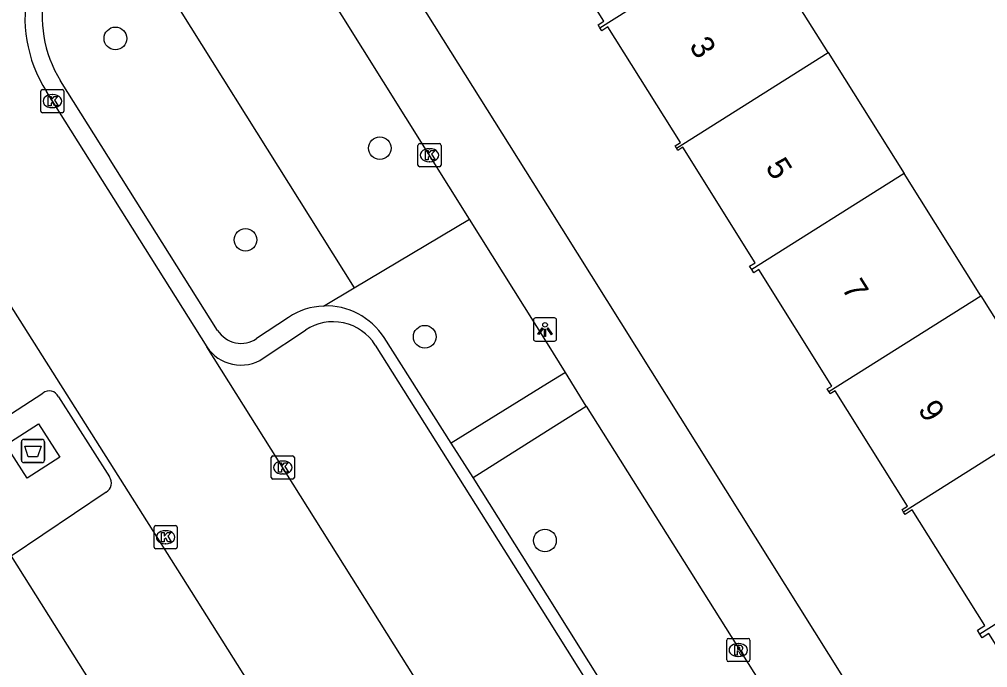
# Model space of a CAD drawing. Extents: x 160077 to 160945, y 386481 to 387498.
# Drawn here: x 160477.21 to 160519, y 386801.35 to 386829.32 of the extents above; entities that cross this region are included whole.
import ezdxf

# ---------------------------------------------------------------- set-up
doc = ezdxf.new("R2010")
doc.units = 0
for name, color, linetype in [('IMGEO_Afval_apart_plaats', 7, 'Continuous'), ('IMGEO_Boom', 7, 'Continuous'), ('IMGEO_Groenvoorziening', 7, 'Continuous'), ('IMGEO_Kolk', 7, 'Continuous'), ('IMGEO_Lichtpunt', 7, 'Continuous'), ('IMGEO_Pand', 7, 'Continuous'), ('IMGEO_Pand_nummerreeks', 7, 'Continuous'), ('IMGEO_Rijbaan_lokaal_open', 7, 'Continuous'), ('IMGEO_Rioolput', 7, 'Continuous'), ('IMGEO_Voetpad_gesloten', 7, 'Continuous'), ('IMGEO_Voetpad_open', 7, 'Continuous')]:
    doc.layers.add(name, color=color, linetype=linetype)

msp = doc.modelspace()

# ---------------------------------------------------------------- linework, layer by layer
at = {"layer": 'IMGEO_Afval_apart_plaats'}
for p, q in [((160477.3, 386810.299), (160477.3, 386811.099)), ((160477.3, 386811.099), (160477.3, 386810.299)), ((160477.4, 386811.199), (160478.19, 386811.199)), ((160478.19, 386811.199), (160477.4, 386811.199)), ((160478.29, 386811.099), (160478.29, 386810.299)), ((160478.29, 386810.299), (160478.29, 386811.099)), ((160478.19, 386810.199), (160477.4, 386810.199)), ((160477.4, 386810.199), (160478.19, 386810.199))]:
    msp.add_line(p, q, dxfattribs=at)
msp.add_lwpolyline([(160477.443, 386810.913), (160478.147, 386810.913), (160477.998, 386810.443), (160477.592, 386810.443), (160477.443, 386810.913)], dxfattribs=at)
for centre, start, end in [((160477.4, 386811.099), 90, 180), ((160477.4, 386811.099), 90, 180), ((160478.19, 386811.099), 0, 90), ((160478.19, 386811.099), 360, 90), ((160477.4, 386810.299), 180, 270), ((160477.4, 386810.299), 180, 270), ((160478.19, 386810.299), 270, 0), ((160478.19, 386810.299), 270, 0)]:
    msp.add_arc(centre, 0.1, start, end, dxfattribs=at)
at = {"layer": 'IMGEO_Boom'}
for centre in [(160481.353, 386828.501), (160492.77, 386823.766), (160486.971, 386819.81), (160494.706, 386815.629), (160499.897, 386806.838)]:
    msp.add_circle(centre, 0.489, dxfattribs=at)
at = {"layer": 'IMGEO_Groenvoorziening'}
for points in [[(160481.322, 386834.24), (160491.654, 386817.735)], [(160491.654, 386817.735), (160496.638, 386820.704)], [(160490.344, 386816.955), (160491.654, 386817.735)]]:
    msp.add_lwpolyline(points, dxfattribs=at)
at = {"layer": 'IMGEO_Kolk'}
for p, q in [((160478.209, 386826.294), (160479.061, 386826.294)), ((160478.134, 386825.368), (160478.134, 386826.22)), ((160478.622, 386826.074), (160478.647, 386826.074)), ((160479.135, 386826.22), (160479.135, 386825.368)), ((160478.645, 386825.514), (160478.62, 386825.514)), ((160479.061, 386825.294), (160478.209, 386825.294)), ((160494.413, 386823.035), (160494.413, 386823.887)), ((160494.488, 386823.961), (160495.34, 386823.961)), ((160495.414, 386823.887), (160495.414, 386823.035)), ((160494.901, 386823.741), (160494.926, 386823.741)), ((160495.34, 386822.961), (160494.488, 386822.961)), ((160494.924, 386823.181), (160494.899, 386823.181)), ((160488.079, 386809.562), (160488.079, 386810.414)), ((160488.154, 386810.488), (160489.006, 386810.488)), ((160489.08, 386810.414), (160489.08, 386809.562)), ((160488.567, 386810.268), (160488.592, 386810.268)), ((160488.59, 386809.708), (160488.565, 386809.708)), ((160489.006, 386809.488), (160488.154, 386809.488)), ((160483.098, 386807.48), (160483.95, 386807.48)), ((160483.023, 386806.554), (160483.023, 386807.406)), ((160483.511, 386807.26), (160483.536, 386807.26)), ((160484.024, 386807.406), (160484.024, 386806.554)), ((160483.534, 386806.7), (160483.509, 386806.7)), ((160483.95, 386806.48), (160483.098, 386806.48))]:
    msp.add_line(p, q, dxfattribs=at)
for points in [[(160478.209, 386826.294), (160479.061, 386826.294)], [(160478.134, 386825.368), (160478.134, 386826.22)], [(160478.455, 386825.994), (160478.578, 386825.994), (160478.578, 386825.843), (160478.708, 386825.994), (160478.872, 386825.994), (160478.726, 386825.843), (160478.879, 386825.594), (160478.727, 386825.594), (160478.642, 386825.758), (160478.578, 386825.691), (160478.578, 386825.594), (160478.455, 386825.594), (160478.455, 386825.994)], [(160479.135, 386826.22), (160479.135, 386825.368)], [(160479.061, 386825.294), (160478.209, 386825.294)], [(160494.413, 386823.035), (160494.413, 386823.887)], [(160494.488, 386823.961), (160495.34, 386823.961)], [(160495.414, 386823.887), (160495.414, 386823.035)], [(160494.734, 386823.661), (160494.857, 386823.661), (160494.857, 386823.51), (160494.987, 386823.661), (160495.151, 386823.661), (160495.005, 386823.51), (160495.158, 386823.261), (160495.006, 386823.261), (160494.921, 386823.425), (160494.857, 386823.358), (160494.857, 386823.261), (160494.734, 386823.261), (160494.734, 386823.661)], [(160495.34, 386822.961), (160494.488, 386822.961)], [(160488.079, 386809.562), (160488.079, 386810.414)], [(160488.154, 386810.488), (160489.006, 386810.488)], [(160489.08, 386810.414), (160489.08, 386809.562)], [(160488.4, 386810.188), (160488.523, 386810.188), (160488.523, 386810.037), (160488.653, 386810.188), (160488.817, 386810.188), (160488.671, 386810.037), (160488.824, 386809.788), (160488.672, 386809.788), (160488.587, 386809.952), (160488.523, 386809.885), (160488.523, 386809.788), (160488.4, 386809.788), (160488.4, 386810.188)], [(160489.006, 386809.488), (160488.154, 386809.488)], [(160483.098, 386807.48), (160483.95, 386807.48)], [(160483.023, 386806.554), (160483.023, 386807.406)], [(160483.344, 386807.18), (160483.467, 386807.18), (160483.467, 386807.029), (160483.597, 386807.18), (160483.761, 386807.18), (160483.615, 386807.029), (160483.768, 386806.78), (160483.616, 386806.78), (160483.531, 386806.944), (160483.467, 386806.877), (160483.467, 386806.78), (160483.344, 386806.78), (160483.344, 386807.18)], [(160484.024, 386807.406), (160484.024, 386806.554)], [(160483.95, 386806.48), (160483.098, 386806.48)]]:
    msp.add_lwpolyline(points, dxfattribs=at)
for centre, start, end in [((160478.211, 386826.218), 91.552, 178.448), ((160478.211, 386826.218), 91.552, 178.448), ((160479.059, 386826.218), 1.552, 88.448), ((160479.059, 386826.218), 1.552, 88.448), ((160478.211, 386825.37), 181.552, 268.448), ((160478.211, 386825.37), 181.552, 268.448), ((160479.059, 386825.37), 271.552, 358.448), ((160479.059, 386825.37), 271.552, 358.448), ((160494.49, 386823.885), 91.552, 178.448), ((160494.49, 386823.885), 91.552, 178.448), ((160495.338, 386823.885), 1.552, 88.448), ((160495.338, 386823.885), 1.552, 88.448), ((160494.49, 386823.037), 181.552, 268.448), ((160494.49, 386823.037), 181.552, 268.448), ((160495.338, 386823.037), 271.552, 358.448), ((160495.338, 386823.037), 271.552, 358.448), ((160488.156, 386810.412), 91.552, 178.448), ((160488.156, 386810.412), 91.552, 178.448), ((160489.004, 386810.412), 1.552, 88.448), ((160489.004, 386810.412), 1.552, 88.448), ((160488.156, 386809.564), 181.552, 268.448), ((160488.156, 386809.564), 181.552, 268.448), ((160489.004, 386809.564), 271.552, 358.448), ((160489.004, 386809.564), 271.552, 358.448), ((160483.1, 386807.404), 91.552, 178.448), ((160483.1, 386807.404), 91.552, 178.448), ((160483.948, 386807.404), 1.552, 88.448), ((160483.948, 386807.404), 1.552, 88.448), ((160483.1, 386806.556), 181.552, 268.448), ((160483.1, 386806.556), 181.552, 268.448), ((160483.948, 386806.556), 271.552, 358.448), ((160483.948, 386806.556), 271.552, 358.448)]:
    msp.add_arc(centre, 0.0765, start, end, dxfattribs=at)
for centre, major_axis, ratio, start_param, end_param in [((160478.621, 386825.794), (-0.387, 0.002), 0.722429, 4.712389, 7.853982), ((160478.646, 386825.794), (-0.39, 0.002), 0.717154, 1.570796, 4.712389), ((160494.9, 386823.461), (-0.387, 0.002), 0.722429, 4.712389, 7.853982), ((160494.925, 386823.461), (-0.39, 0.002), 0.717154, 1.570796, 4.712389), ((160488.566, 386809.988), (-0.387, 0.002), 0.722429, 4.712389, 7.853982), ((160488.591, 386809.988), (-0.39, 0.002), 0.717154, 1.570796, 4.712389), ((160483.51, 386806.98), (-0.387, 0.002), 0.722429, 4.712389, 7.853982), ((160483.535, 386806.98), (-0.39, 0.002), 0.717154, 1.570796, 4.712389)]:
    msp.add_ellipse(centre, major_axis=major_axis, ratio=ratio, start_param=start_param, end_param=end_param, dxfattribs=at)
at = {"layer": 'IMGEO_Lichtpunt'}
for p, q in [((160499.4, 386816.345), (160499.4, 386815.538)), ((160499.4, 386816.345), (160499.4, 386815.538)), ((160500.302, 386816.44), (160499.494, 386816.44)), ((160500.302, 386816.44), (160499.494, 386816.44)), ((160500.396, 386815.538), (160500.396, 386816.345)), ((160500.396, 386815.538), (160500.396, 386816.345)), ((160499.494, 386815.444), (160500.302, 386815.444)), ((160499.494, 386815.444), (160500.302, 386815.444))]:
    msp.add_line(p, q, dxfattribs=at)
for points in [[(160499.774, 386816.009), (160499.813, 386815.981), (160499.625, 386815.719), (160499.587, 386815.746), (160499.774, 386816.009)], [(160499.876, 386815.961), (160499.923, 386815.961), (160499.923, 386815.639), (160499.876, 386815.639), (160499.876, 386815.961)], [(160499.986, 386815.981), (160500.024, 386816.008), (160500.211, 386815.746), (160500.172, 386815.718), (160499.986, 386815.981)]]:
    msp.add_lwpolyline(points, dxfattribs=at)
msp.add_circle((160499.899, 386816.143), 0.0994, dxfattribs=at)
for centre, start, end in [((160499.494, 386816.345), 90, 180), ((160499.494, 386816.345), 90, 180), ((160500.302, 386816.345), 0, 90), ((160500.302, 386816.345), 0, 90), ((160499.494, 386815.538), 180, 270), ((160499.494, 386815.538), 180, 270), ((160500.302, 386815.538), 270, 0), ((160500.302, 386815.538), 270, 360)]:
    msp.add_arc(centre, 0.0946, start, end, dxfattribs=at)
at = {"layer": 'IMGEO_Pand'}
for points in [[(160502.266, 386828.963), (160502.185, 386829.092), (160502.435, 386829.249), (160500, 386833.124), (160499.363, 386834.138), (160499.106, 386833.977), (160498.914, 386834.282)], [(160502.266, 386828.963), (160508.843, 386833.1)], [(160512.119, 386827.886), (160508.843, 386833.1)], [(160505.576, 386823.77), (160505.519, 386823.871), (160505.748, 386824.014), (160502.614, 386829.002), (160502.347, 386828.834), (160502.266, 386828.963)], [(160505.576, 386823.77), (160512.119, 386827.886)], [(160512.119, 386827.886), (160515.396, 386822.67)], [(160508.819, 386818.533), (160508.73, 386818.675), (160508.967, 386818.824), (160505.84, 386823.802), (160505.632, 386823.671), (160505.576, 386823.77)], [(160515.396, 386822.67), (160508.819, 386818.533)], [(160518.708, 386817.399), (160515.396, 386822.67)], [(160512.142, 386813.268), (160512.075, 386813.375), (160512.279, 386813.502), (160509.122, 386818.527), (160508.907, 386818.392), (160508.819, 386818.533)], [(160512.142, 386813.268), (160518.708, 386817.399)], [(160518.708, 386817.399), (160521.966, 386812.214)], [(160515.374, 386808.067), (160515.308, 386808.172), (160515.545, 386808.321), (160512.422, 386813.292), (160512.211, 386813.16), (160512.142, 386813.268)], [(160521.966, 386812.214), (160515.374, 386808.067)], [(160518.66, 386802.802), (160518.558, 386802.965), (160518.876, 386803.165), (160515.741, 386808.154), (160515.439, 386807.964), (160515.374, 386808.067)], [(160525.268, 386806.959), (160518.66, 386802.802)], [(160521.94, 386797.63), (160521.849, 386797.775), (160522.115, 386797.942), (160519.049, 386802.821), (160518.762, 386802.64), (160518.66, 386802.802)]]:
    msp.add_lwpolyline(points, dxfattribs=at)
at = {"layer": 'IMGEO_Rijbaan_lokaal_open'}
for points in [[(160478.374, 386826.207), (160485.3, 386815.198)], [(160516.389, 386754.32), (160513.375, 386759.047), (160512.49, 386760.505), (160506.313, 386770.262), (160484.216, 386805.302), (160473.247, 386822.633)], [(160521.564, 386757.591), (160509.431, 386776.805), (160500, 386791.819), (160493.709, 386801.834), (160485.3, 386815.198)]]:
    msp.add_lwpolyline(points, dxfattribs=at)
msp.add_arc((160483.461, 386829.406), 6.009, 122.9331, 212.1654, dxfattribs=at)
at = {"layer": 'IMGEO_Rioolput'}
for p, q in [((160507.74, 386801.685), (160507.74, 386802.537)), ((160507.815, 386802.611), (160508.667, 386802.611)), ((160508.741, 386802.537), (160508.741, 386801.685)), ((160508.228, 386802.391), (160508.253, 386802.391)), ((160508.667, 386801.611), (160507.815, 386801.611)), ((160508.251, 386801.831), (160508.226, 386801.831))]:
    msp.add_line(p, q, dxfattribs=at)
for points in [[(160507.74, 386801.685), (160507.74, 386802.537)], [(160507.815, 386802.611), (160508.667, 386802.611)], [(160508.741, 386802.537), (160508.741, 386801.685)], [(160508.329, 386802.309), (160508.077, 386802.311), (160508.077, 386801.911)], [(160508.077, 386801.911), (160508.201, 386801.911), (160508.201, 386802.073), (160508.212, 386802.073)], [(160508.255, 386802.23), (160508.201, 386802.23), (160508.201, 386802.149)], [(160508.201, 386802.149), (160508.253, 386802.149)], [(160508.259, 386802.044), (160508.33, 386801.911), (160508.47, 386801.911), (160508.405, 386802.037)], [(160508.667, 386801.611), (160507.815, 386801.611)]]:
    msp.add_lwpolyline(points, dxfattribs=at)
for centre, radius, start, end in [((160507.817, 386802.535), 0.0765, 91.552, 178.448), ((160507.817, 386802.535), 0.0765, 91.552, 178.448), ((160508.665, 386802.535), 0.0765, 1.552, 88.448), ((160508.665, 386802.535), 0.0765, 1.552, 88.448), ((160508.211, 386802.02), 0.0533, 26.0293, 88.6989), ((160508.237, 386802.338), 0.19, 274.7715, 282.9687), ((160508.261, 386802.134), 0.0964, 77.0061, 93.1865), ((160508.275, 386802.191), 0.0378, 276.6634, 79.6772), ((160508.328, 386802.199), 0.109, 350.3612, 89.416), ((160508.326, 386802.199), 0.112, 277.5842, 350.9817), ((160508.31, 386801.984), 0.108, 29.5134, 73.7905), ((160507.817, 386801.687), 0.0765, 181.552, 268.448), ((160507.817, 386801.687), 0.0765, 181.552, 268.448), ((160508.665, 386801.687), 0.0765, 271.552, 358.448), ((160508.665, 386801.687), 0.0765, 271.552, 358.448)]:
    msp.add_arc(centre, radius, start, end, dxfattribs=at)
for centre, major_axis, ratio, start_param, end_param in [((160508.227, 386802.111), (-0.387, 0.002), 0.722429, 4.712389, 7.853982), ((160508.252, 386802.111), (-0.39, 0.002), 0.717154, 1.570796, 4.712389)]:
    msp.add_ellipse(centre, major_axis=major_axis, ratio=ratio, start_param=start_param, end_param=end_param, dxfattribs=at)
at = {"layer": 'IMGEO_Voetpad_gesloten'}
msp.add_lwpolyline([(160476.631, 386810.965), (160478.039, 386811.868), (160478.959, 386810.433), (160477.551, 386809.53), (160476.631, 386810.965)], dxfattribs=at)
at = {"layer": 'IMGEO_Voetpad_open'}
for points in [[(160496.638, 386820.704), (160487.431, 386835.412)], [(160493.843, 386831.09), (160500, 386821.271), (160533.22, 386768.294)], [(160485.767, 386815.905), (160478.99, 386826.674)], [(160500.779, 386814.089), (160500, 386815.333), (160496.638, 386820.704)], [(160488.824, 386816.462), (160487.451, 386815.546)], [(160487.736, 386814.7), (160489.559, 386815.915)], [(160495.843, 386811.033), (160492.95, 386815.59)], [(160492.571, 386815.272), (160500, 386803.462), (160525.691, 386762.559)], [(160500.779, 386814.089), (160500, 386813.607), (160495.843, 386811.033)], [(160501.675, 386812.637), (160500.779, 386814.089)], [(160474.106, 386810.535), (160478.227, 386813.191)], [(160478.896, 386813.039), (160481.102, 386809.578)], [(160496.797, 386809.553), (160500, 386811.578), (160501.675, 386812.637)], [(160501.675, 386812.637), (160511.177, 386797.531)], [(160496.797, 386809.553), (160495.843, 386811.033)], [(160506.249, 386794.478), (160500, 386804.445), (160496.797, 386809.553)], [(160480.957, 386808.924), (160476.862, 386806.156)], [(160476.862, 386806.156), (160492.749, 386780.913), (160500, 386769.417), (160507.532, 386757.475), (160511.203, 386759.837)]]:
    msp.add_lwpolyline(points, dxfattribs=at)
for centre, radius, start, end in [((160483.357, 386829.421), 5.159, 122.445, 212.1711), ((160490.455, 386814.022), 2.935, 92.1734, 123.7667), ((160490.462, 386814.009), 2.948, 32.4254, 92.2842), ((160490.752, 386814.127), 2.149, 32.1876, 123.7112), ((160486.784, 386816.545), 1.201, 212.1808, 303.7505), ((160486.765, 386816.155), 1.75, 213.1639, 303.7282), ((160478.503, 386812.856), 0.434, 24.9492, 129.4496), ((160480.732, 386809.317), 0.453, 299.8205, 35.1776)]:
    msp.add_arc(centre, radius, start, end, dxfattribs=at)

# ---------------------------------------------------------------- texts
at = {"layer": 'IMGEO_Pand_nummerreeks'}
for s, p in [('3', (160506.094, 386828.177)), ('5', (160509.385, 386822.949)), ('7', (160512.676, 386817.721)), ('9', (160515.967, 386812.494))]:
    msp.add_text(s, height=1, rotation=302.1919, dxfattribs=at).set_placement(p)

doc.saveas('drawing.dxf')
